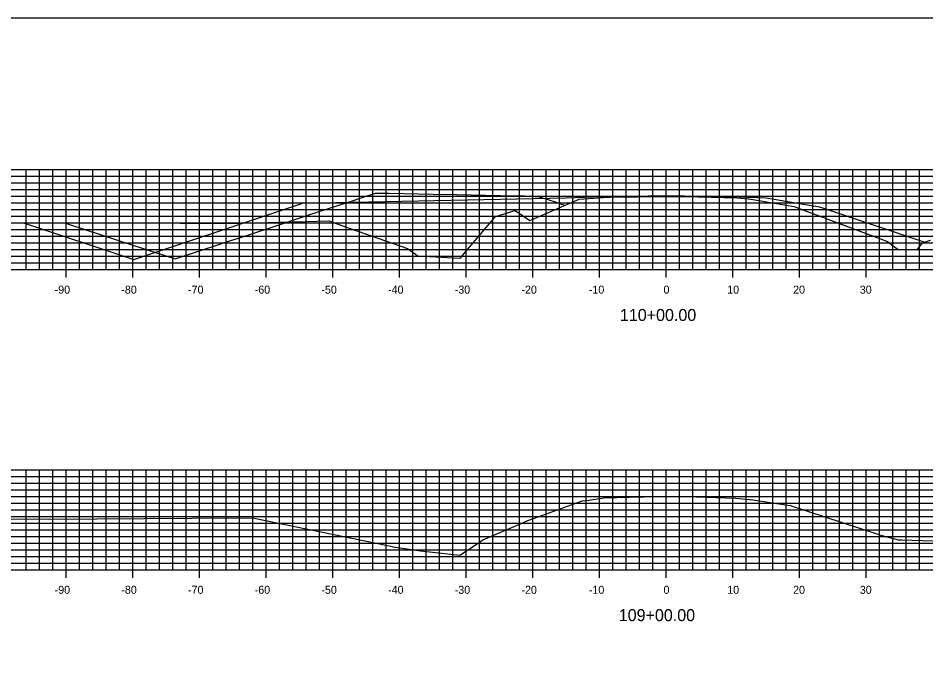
# Model space of a CAD drawing. Extents: x 1661012 to 1662122, y 670053 to 671852.
# Drawn here: x 1661094.8 to 1661230.9, y 671370.5 to 671466.8 of the extents above; entities that cross this region are included whole.
import ezdxf

# ---------------------------------------------------------------- set-up
doc = ezdxf.new("R2010")
doc.units = 0
for name, color, linetype in [('R_Concrete', 7, 'Continuous'), ('R_Concrete Hidden', 7, 'Continuous'), ('R_Erosion', 7, 'Continuous'), ('R_Exist Surface', 7, 'Continuous'), ('R_Proposed Road', 7, 'Continuous'), ('R_ROW Annot', 7, 'Continuous')]:
    doc.layers.add(name, color=color, linetype=linetype)

msp = doc.modelspace()

# ---------------------------------------------------------------- linework, layer by layer
at = {"layer": 'R_Concrete'}
for p, q in [((1661041.99, 671444.12), (1661341.99, 671444.12)), ((1661041.99, 671443.12), (1661341.99, 671443.12)), ((1661095.99, 671429.12), (1661095.99, 671444.12)), ((1661097.99, 671429.12), (1661097.99, 671444.12)), ((1661099.99, 671429.12), (1661099.99, 671444.12)), ((1661101.99, 671429.12), (1661101.99, 671444.12)), ((1661103.99, 671429.12), (1661103.99, 671444.12)), ((1661105.99, 671429.12), (1661105.99, 671444.12)), ((1661107.99, 671429.12), (1661107.99, 671444.12)), ((1661109.99, 671429.12), (1661109.99, 671444.12)), ((1661111.99, 671429.12), (1661111.99, 671444.12)), ((1661113.99, 671429.12), (1661113.99, 671444.12)), ((1661115.99, 671429.12), (1661115.99, 671444.12)), ((1661117.99, 671429.12), (1661117.99, 671444.12)), ((1661119.99, 671429.12), (1661119.99, 671444.12)), ((1661121.99, 671429.12), (1661121.99, 671444.12)), ((1661123.99, 671429.12), (1661123.99, 671444.12)), ((1661125.99, 671429.12), (1661125.99, 671444.12)), ((1661127.99, 671429.12), (1661127.99, 671444.12)), ((1661129.99, 671429.12), (1661129.99, 671444.12)), ((1661131.99, 671429.12), (1661131.99, 671444.12)), ((1661133.99, 671429.12), (1661133.99, 671444.12)), ((1661135.99, 671429.12), (1661135.99, 671444.12)), ((1661137.99, 671429.12), (1661137.99, 671444.12)), ((1661139.99, 671429.12), (1661139.99, 671444.12)), ((1661141.99, 671429.12), (1661141.99, 671444.12)), ((1661143.99, 671429.12), (1661143.99, 671444.12)), ((1661145.99, 671429.12), (1661145.99, 671444.12)), ((1661147.99, 671429.12), (1661147.99, 671444.12)), ((1661149.99, 671429.12), (1661149.99, 671444.12)), ((1661151.99, 671429.12), (1661151.99, 671444.12)), ((1661153.99, 671429.12), (1661153.99, 671444.12)), ((1661155.99, 671429.12), (1661155.99, 671444.12)), ((1661157.99, 671429.12), (1661157.99, 671444.12)), ((1661159.99, 671429.12), (1661159.99, 671444.12)), ((1661161.99, 671429.12), (1661161.99, 671444.12)), ((1661163.99, 671429.12), (1661163.99, 671444.12)), ((1661165.99, 671429.12), (1661165.99, 671444.12)), ((1661167.99, 671429.12), (1661167.99, 671444.12)), ((1661169.99, 671429.12), (1661169.99, 671444.12)), ((1661171.99, 671429.12), (1661171.99, 671444.12)), ((1661173.99, 671429.12), (1661173.99, 671444.12)), ((1661175.99, 671429.12), (1661175.99, 671444.12)), ((1661177.99, 671429.12), (1661177.99, 671444.12)), ((1661179.99, 671429.12), (1661179.99, 671444.12)), ((1661181.99, 671429.12), (1661181.99, 671444.12)), ((1661183.99, 671429.12), (1661183.99, 671444.12)), ((1661185.99, 671429.12), (1661185.99, 671444.12)), ((1661187.99, 671429.12), (1661187.99, 671444.12)), ((1661189.99, 671429.12), (1661189.99, 671444.12)), ((1661191.99, 671429.12), (1661191.99, 671444.12)), ((1661193.99, 671429.12), (1661193.99, 671444.12)), ((1661195.99, 671429.12), (1661195.99, 671444.12)), ((1661197.99, 671429.12), (1661197.99, 671444.12)), ((1661199.99, 671429.12), (1661199.99, 671444.12)), ((1661201.99, 671429.12), (1661201.99, 671444.12)), ((1661203.99, 671429.12), (1661203.99, 671444.12)), ((1661205.99, 671429.12), (1661205.99, 671444.12)), ((1661207.99, 671429.12), (1661207.99, 671444.12)), ((1661209.99, 671429.12), (1661209.99, 671444.12)), ((1661211.99, 671429.12), (1661211.99, 671444.12)), ((1661213.99, 671429.12), (1661213.99, 671444.12)), ((1661215.99, 671429.12), (1661215.99, 671444.12)), ((1661217.99, 671429.12), (1661217.99, 671444.12)), ((1661219.99, 671429.12), (1661219.99, 671444.12)), ((1661221.99, 671429.12), (1661221.99, 671444.12)), ((1661223.99, 671429.12), (1661223.99, 671444.12)), ((1661225.99, 671429.12), (1661225.99, 671444.12)), ((1661227.99, 671429.12), (1661227.99, 671444.12)), ((1661229.99, 671429.12), (1661229.99, 671444.12)), ((1661041.99, 671442.12), (1661341.99, 671442.12)), ((1661041.99, 671441.12), (1661341.99, 671441.12)), ((1661041.99, 671440.12), (1661341.99, 671440.12)), ((1661041.99, 671439.12), (1661341.99, 671439.12)), ((1661041.99, 671438.12), (1661341.99, 671438.12)), ((1661041.99, 671437.12), (1661341.99, 671437.12)), ((1661041.99, 671436.12), (1661341.99, 671436.12)), ((1661041.99, 671435.12), (1661341.99, 671435.12)), ((1661041.99, 671434.12), (1661341.99, 671434.12)), ((1661041.99, 671433.12), (1661341.99, 671433.12)), ((1661041.99, 671432.12), (1661341.99, 671432.12)), ((1661041.99, 671431.12), (1661341.99, 671431.12)), ((1661041.99, 671430.12), (1661341.99, 671430.12)), ((1661095.99, 671429.12), (1661095.99, 671429.72)), ((1661097.99, 671429.12), (1661097.99, 671429.72)), ((1661099.99, 671429.12), (1661099.99, 671429.72)), ((1661101.99, 671427.92), (1661101.99, 671430.32)), ((1661103.99, 671429.12), (1661103.99, 671429.72)), ((1661105.99, 671429.12), (1661105.99, 671429.72)), ((1661107.99, 671429.12), (1661107.99, 671429.72)), ((1661109.99, 671429.12), (1661109.99, 671429.72)), ((1661111.99, 671427.92), (1661111.99, 671430.32)), ((1661113.99, 671429.12), (1661113.99, 671429.72)), ((1661115.99, 671429.12), (1661115.99, 671429.72)), ((1661117.99, 671429.12), (1661117.99, 671429.72)), ((1661119.99, 671429.12), (1661119.99, 671429.72)), ((1661121.99, 671427.92), (1661121.99, 671430.32)), ((1661123.99, 671429.12), (1661123.99, 671429.72)), ((1661125.99, 671429.12), (1661125.99, 671429.72)), ((1661127.99, 671429.12), (1661127.99, 671429.72)), ((1661129.99, 671429.12), (1661129.99, 671429.72)), ((1661131.99, 671427.92), (1661131.99, 671430.32)), ((1661133.99, 671429.12), (1661133.99, 671429.72)), ((1661135.99, 671429.12), (1661135.99, 671429.72)), ((1661137.99, 671429.12), (1661137.99, 671429.72)), ((1661139.99, 671429.12), (1661139.99, 671429.72)), ((1661141.99, 671427.92), (1661141.99, 671430.32)), ((1661143.99, 671429.12), (1661143.99, 671429.72)), ((1661145.99, 671429.12), (1661145.99, 671429.72)), ((1661147.99, 671429.12), (1661147.99, 671429.72)), ((1661149.99, 671429.12), (1661149.99, 671429.72)), ((1661151.99, 671427.92), (1661151.99, 671430.32)), ((1661153.99, 671429.12), (1661153.99, 671429.72)), ((1661155.99, 671429.12), (1661155.99, 671429.72)), ((1661157.99, 671429.12), (1661157.99, 671429.72)), ((1661159.99, 671429.12), (1661159.99, 671429.72)), ((1661161.99, 671427.92), (1661161.99, 671430.32)), ((1661163.99, 671429.12), (1661163.99, 671429.72)), ((1661165.99, 671429.12), (1661165.99, 671429.72)), ((1661167.99, 671429.12), (1661167.99, 671429.72)), ((1661169.99, 671429.12), (1661169.99, 671429.72)), ((1661171.99, 671427.92), (1661171.99, 671430.32)), ((1661173.99, 671429.12), (1661173.99, 671429.72)), ((1661175.99, 671429.12), (1661175.99, 671429.72)), ((1661177.99, 671429.12), (1661177.99, 671429.72)), ((1661179.99, 671429.12), (1661179.99, 671429.72)), ((1661181.99, 671427.92), (1661181.99, 671430.32)), ((1661183.99, 671429.12), (1661183.99, 671429.72)), ((1661185.99, 671429.12), (1661185.99, 671429.72)), ((1661187.99, 671429.12), (1661187.99, 671429.72)), ((1661189.99, 671429.12), (1661189.99, 671429.72)), ((1661191.99, 671427.92), (1661191.99, 671430.32)), ((1661193.99, 671429.12), (1661193.99, 671429.72)), ((1661195.99, 671429.12), (1661195.99, 671429.72)), ((1661197.99, 671429.12), (1661197.99, 671429.72)), ((1661199.99, 671429.12), (1661199.99, 671429.72)), ((1661201.99, 671427.92), (1661201.99, 671430.32)), ((1661203.99, 671429.12), (1661203.99, 671429.72)), ((1661205.99, 671429.12), (1661205.99, 671429.72)), ((1661207.99, 671429.12), (1661207.99, 671429.72)), ((1661209.99, 671429.12), (1661209.99, 671429.72)), ((1661211.99, 671427.92), (1661211.99, 671430.32)), ((1661213.99, 671429.12), (1661213.99, 671429.72)), ((1661215.99, 671429.12), (1661215.99, 671429.72)), ((1661217.99, 671429.12), (1661217.99, 671429.72)), ((1661219.99, 671429.12), (1661219.99, 671429.72)), ((1661221.99, 671427.92), (1661221.99, 671430.32)), ((1661223.99, 671429.12), (1661223.99, 671429.72)), ((1661225.99, 671429.12), (1661225.99, 671429.72)), ((1661227.99, 671429.12), (1661227.99, 671429.72)), ((1661229.99, 671429.12), (1661229.99, 671429.72)), ((1661041.99, 671429.12), (1661341.99, 671429.12)), ((1661041.99, 671399.12), (1661341.99, 671399.12)), ((1661041.99, 671398.12), (1661341.99, 671398.12)), ((1661095.99, 671384.12), (1661095.99, 671399.12)), ((1661097.99, 671384.12), (1661097.99, 671399.12)), ((1661099.99, 671384.12), (1661099.99, 671399.12)), ((1661101.99, 671384.12), (1661101.99, 671399.12)), ((1661103.99, 671384.12), (1661103.99, 671399.12)), ((1661105.99, 671384.12), (1661105.99, 671399.12)), ((1661107.99, 671384.12), (1661107.99, 671399.12)), ((1661109.99, 671384.12), (1661109.99, 671399.12)), ((1661111.99, 671384.12), (1661111.99, 671399.12)), ((1661113.99, 671384.12), (1661113.99, 671399.12)), ((1661115.99, 671384.12), (1661115.99, 671399.12)), ((1661117.99, 671384.12), (1661117.99, 671399.12)), ((1661119.99, 671384.12), (1661119.99, 671399.12)), ((1661121.99, 671384.12), (1661121.99, 671399.12)), ((1661123.99, 671384.12), (1661123.99, 671399.12)), ((1661125.99, 671384.12), (1661125.99, 671399.12)), ((1661127.99, 671384.12), (1661127.99, 671399.12)), ((1661129.99, 671384.12), (1661129.99, 671399.12)), ((1661131.99, 671384.12), (1661131.99, 671399.12)), ((1661133.99, 671384.12), (1661133.99, 671399.12)), ((1661135.99, 671384.12), (1661135.99, 671399.12)), ((1661137.99, 671384.12), (1661137.99, 671399.12)), ((1661139.99, 671384.12), (1661139.99, 671399.12)), ((1661141.99, 671384.12), (1661141.99, 671399.12)), ((1661143.99, 671384.12), (1661143.99, 671399.12)), ((1661145.99, 671384.12), (1661145.99, 671399.12)), ((1661147.99, 671384.12), (1661147.99, 671399.12)), ((1661149.99, 671384.12), (1661149.99, 671399.12)), ((1661151.99, 671384.12), (1661151.99, 671399.12)), ((1661153.99, 671384.12), (1661153.99, 671399.12)), ((1661155.99, 671384.12), (1661155.99, 671399.12)), ((1661157.99, 671384.12), (1661157.99, 671399.12)), ((1661159.99, 671384.12), (1661159.99, 671399.12)), ((1661161.99, 671384.12), (1661161.99, 671399.12)), ((1661163.99, 671384.12), (1661163.99, 671399.12)), ((1661165.99, 671384.12), (1661165.99, 671399.12)), ((1661167.99, 671384.12), (1661167.99, 671399.12)), ((1661169.99, 671384.12), (1661169.99, 671399.12)), ((1661171.99, 671384.12), (1661171.99, 671399.12)), ((1661173.99, 671384.12), (1661173.99, 671399.12)), ((1661175.99, 671384.12), (1661175.99, 671399.12)), ((1661177.99, 671384.12), (1661177.99, 671399.12)), ((1661179.99, 671384.12), (1661179.99, 671399.12)), ((1661181.99, 671384.12), (1661181.99, 671399.12)), ((1661183.99, 671384.12), (1661183.99, 671399.12)), ((1661185.99, 671384.12), (1661185.99, 671399.12)), ((1661187.99, 671384.12), (1661187.99, 671399.12)), ((1661189.99, 671384.12), (1661189.99, 671399.12)), ((1661191.99, 671384.12), (1661191.99, 671399.12)), ((1661193.99, 671384.12), (1661193.99, 671399.12)), ((1661195.99, 671384.12), (1661195.99, 671399.12)), ((1661197.99, 671384.12), (1661197.99, 671399.12)), ((1661199.99, 671384.12), (1661199.99, 671399.12)), ((1661201.99, 671384.12), (1661201.99, 671399.12)), ((1661203.99, 671384.12), (1661203.99, 671399.12)), ((1661205.99, 671384.12), (1661205.99, 671399.12)), ((1661207.99, 671384.12), (1661207.99, 671399.12)), ((1661209.99, 671384.12), (1661209.99, 671399.12)), ((1661211.99, 671384.12), (1661211.99, 671399.12)), ((1661213.99, 671384.12), (1661213.99, 671399.12)), ((1661215.99, 671384.12), (1661215.99, 671399.12)), ((1661217.99, 671384.12), (1661217.99, 671399.12)), ((1661219.99, 671384.12), (1661219.99, 671399.12)), ((1661221.99, 671384.12), (1661221.99, 671399.12)), ((1661223.99, 671384.12), (1661223.99, 671399.12)), ((1661225.99, 671384.12), (1661225.99, 671399.12)), ((1661227.99, 671384.12), (1661227.99, 671399.12)), ((1661229.99, 671384.12), (1661229.99, 671399.12)), ((1661041.99, 671397.12), (1661341.99, 671397.12)), ((1661041.99, 671396.12), (1661341.99, 671396.12)), ((1661041.99, 671395.12), (1661341.99, 671395.12)), ((1661041.99, 671394.12), (1661341.99, 671394.12)), ((1661041.99, 671393.12), (1661341.99, 671393.12)), ((1661041.99, 671392.12), (1661341.99, 671392.12)), ((1661041.99, 671391.12), (1661341.99, 671391.12)), ((1661041.99, 671390.12), (1661341.99, 671390.12)), ((1661041.99, 671389.12), (1661341.99, 671389.12)), ((1661041.99, 671388.12), (1661341.99, 671388.12)), ((1661041.99, 671387.12), (1661341.99, 671387.12)), ((1661041.99, 671386.12), (1661341.99, 671386.12)), ((1661041.99, 671385.12), (1661341.99, 671385.12)), ((1661095.99, 671384.12), (1661095.99, 671384.72)), ((1661097.99, 671384.12), (1661097.99, 671384.72)), ((1661099.99, 671384.12), (1661099.99, 671384.72)), ((1661101.99, 671382.92), (1661101.99, 671385.32)), ((1661103.99, 671384.12), (1661103.99, 671384.72)), ((1661105.99, 671384.12), (1661105.99, 671384.72)), ((1661107.99, 671384.12), (1661107.99, 671384.72)), ((1661109.99, 671384.12), (1661109.99, 671384.72)), ((1661111.99, 671382.92), (1661111.99, 671385.32)), ((1661113.99, 671384.12), (1661113.99, 671384.72)), ((1661115.99, 671384.12), (1661115.99, 671384.72)), ((1661117.99, 671384.12), (1661117.99, 671384.72)), ((1661119.99, 671384.12), (1661119.99, 671384.72)), ((1661121.99, 671382.92), (1661121.99, 671385.32)), ((1661123.99, 671384.12), (1661123.99, 671384.72)), ((1661125.99, 671384.12), (1661125.99, 671384.72)), ((1661127.99, 671384.12), (1661127.99, 671384.72)), ((1661129.99, 671384.12), (1661129.99, 671384.72)), ((1661131.99, 671382.92), (1661131.99, 671385.32)), ((1661133.99, 671384.12), (1661133.99, 671384.72)), ((1661135.99, 671384.12), (1661135.99, 671384.72)), ((1661137.99, 671384.12), (1661137.99, 671384.72)), ((1661139.99, 671384.12), (1661139.99, 671384.72)), ((1661141.99, 671382.92), (1661141.99, 671385.32)), ((1661143.99, 671384.12), (1661143.99, 671384.72)), ((1661145.99, 671384.12), (1661145.99, 671384.72)), ((1661147.99, 671384.12), (1661147.99, 671384.72)), ((1661149.99, 671384.12), (1661149.99, 671384.72)), ((1661151.99, 671382.92), (1661151.99, 671385.32)), ((1661153.99, 671384.12), (1661153.99, 671384.72)), ((1661155.99, 671384.12), (1661155.99, 671384.72)), ((1661157.99, 671384.12), (1661157.99, 671384.72)), ((1661159.99, 671384.12), (1661159.99, 671384.72)), ((1661161.99, 671382.92), (1661161.99, 671385.32)), ((1661163.99, 671384.12), (1661163.99, 671384.72)), ((1661165.99, 671384.12), (1661165.99, 671384.72)), ((1661167.99, 671384.12), (1661167.99, 671384.72)), ((1661169.99, 671384.12), (1661169.99, 671384.72)), ((1661171.99, 671382.92), (1661171.99, 671385.32)), ((1661173.99, 671384.12), (1661173.99, 671384.72)), ((1661175.99, 671384.12), (1661175.99, 671384.72)), ((1661177.99, 671384.12), (1661177.99, 671384.72)), ((1661179.99, 671384.12), (1661179.99, 671384.72)), ((1661181.99, 671382.92), (1661181.99, 671385.32)), ((1661183.99, 671384.12), (1661183.99, 671384.72)), ((1661185.99, 671384.12), (1661185.99, 671384.72)), ((1661187.99, 671384.12), (1661187.99, 671384.72)), ((1661189.99, 671384.12), (1661189.99, 671384.72)), ((1661191.99, 671382.92), (1661191.99, 671385.32)), ((1661193.99, 671384.12), (1661193.99, 671384.72)), ((1661195.99, 671384.12), (1661195.99, 671384.72)), ((1661197.99, 671384.12), (1661197.99, 671384.72)), ((1661199.99, 671384.12), (1661199.99, 671384.72)), ((1661201.99, 671382.92), (1661201.99, 671385.32)), ((1661203.99, 671384.12), (1661203.99, 671384.72)), ((1661205.99, 671384.12), (1661205.99, 671384.72)), ((1661207.99, 671384.12), (1661207.99, 671384.72)), ((1661209.99, 671384.12), (1661209.99, 671384.72)), ((1661211.99, 671382.92), (1661211.99, 671385.32)), ((1661213.99, 671384.12), (1661213.99, 671384.72)), ((1661215.99, 671384.12), (1661215.99, 671384.72)), ((1661217.99, 671384.12), (1661217.99, 671384.72)), ((1661219.99, 671384.12), (1661219.99, 671384.72)), ((1661221.99, 671382.92), (1661221.99, 671385.32)), ((1661223.99, 671384.12), (1661223.99, 671384.72)), ((1661225.99, 671384.12), (1661225.99, 671384.72)), ((1661227.99, 671384.12), (1661227.99, 671384.72)), ((1661229.99, 671384.12), (1661229.99, 671384.72)), ((1661041.99, 671384.12), (1661341.99, 671384.12))]:
    msp.add_line(p, q, dxfattribs=at)
at = {"layer": 'R_Erosion'}
for points in [[(1661073.27, 671436.14), (1661096.5, 671436.14), (1661103.31, 671436.14), (1661119.17, 671436.08), (1661119.39, 671436.09), (1661126.61, 671436.02), (1661137.83, 671436.34), (1661141.38, 671436.44), (1661144.62, 671435.31), (1661153.18, 671432.3), (1661154.72, 671431.17), (1661160.98, 671430.86), (1661161.17, 671430.87), (1661161.38, 671431.17), (1661166.4, 671437.07), (1661169.36, 671437.99), (1661171.54, 671436.49), (1661177.46, 671439.02), (1661178.92, 671439.66), (1661182.56, 671439.92), (1661183.58, 671439.97), (1661191.8, 671440.07), (1661193.4, 671440.09), (1661194.86, 671440.06), (1661202.62, 671439.87), (1661204.29, 671439.73), (1661204.4, 671439.72), (1661209.14, 671438.91), (1661211.18, 671438.56), (1661211.41, 671438.48), (1661225.17, 671433.36), (1661225.81, 671432.82), (1661226.8, 671432.14), (1661227.48, 671432.14), (1661229.62, 671432.07), (1661229.77, 671432.29), (1661230.45, 671433.14), (1661231.62, 671433.55)], [(1661082.7, 671391.78), (1661099.45, 671391.69), (1661120.84, 671391.86), (1661129.96, 671391.91), (1661150.72, 671387.65), (1661151.3, 671387.52), (1661151.41, 671387.51), (1661155.14, 671386.97), (1661156.49, 671386.81), (1661161.05, 671386.31), (1661163.48, 671387.93), (1661164.49, 671388.61), (1661170.25, 671391.06), (1661171.25, 671391.5), (1661172.22, 671391.85), (1661179.39, 671394.44), (1661180.02, 671394.52), (1661182.7, 671394.9), (1661186.48, 671394.99), (1661193.08, 671395.16), (1661196.54, 671395.05), (1661202.44, 671394.86), (1661204.52, 671394.68), (1661204.58, 671394.67), (1661204.65, 671394.66), (1661210.57, 671393.77), (1661223.59, 671389.49), (1661223.91, 671389.39), (1661223.96, 671389.37), (1661226.76, 671388.62), (1661227.35, 671388.61), (1661236.52, 671388.3)]]:
    msp.add_lwpolyline(points, dxfattribs=at)
at = {"layer": 'R_Exist Surface'}
for p, q in [((1661041.99, 671429.12), (1661341.99, 671429.12)), ((1661041.99, 671384.12), (1661341.99, 671384.12))]:
    msp.add_line(p, q, dxfattribs=at)
at = {"layer": 'R_Proposed Road'}
msp.add_lwpolyline([(1661011.99, 671274.12), (1661371.99, 671274.12), (1661371.99, 671466.82), (1661011.99, 671466.82)], close=True, dxfattribs=at)
at = {"layer": 'R_ROW Annot'}
for points in [[(1661095.62, 671436.14), (1661112.16, 671430.63), (1661137.49, 671439.07), (1661169.58, 671439.71), (1661176.99, 671439.86), (1661180.99, 671440.02), (1661191.99, 671440.24), (1661202.99, 671440.02), (1661206.99, 671439.86), (1661214.4, 671438.63), (1661214.99, 671438.53), (1661230.8, 671433.26)], [(1661101.79, 671436.14), (1661102.09, 671436.04), (1661102.38, 671435.95), (1661111.87, 671432.86), (1661118.37, 671430.75), (1661121.69, 671431.84), (1661125.05, 671432.94), (1661126.72, 671433.48), (1661127.84, 671433.85), (1661132.77, 671435.46), (1661138.26, 671437.26), (1661139.94, 671437.81), (1661144.13, 671439.18), (1661144.31, 671439.23), (1661144.49, 671439.3), (1661146.7, 671440.01), (1661148.4, 671440.57), (1661149.91, 671440.57), (1661150.43, 671440.57), (1661157.06, 671440.43), (1661160.6, 671440.37), (1661169.22, 671440.2), (1661170.13, 671440.18), (1661170.77, 671440.17), (1661172.35, 671440.1), (1661172.8, 671440.09), (1661173.77, 671439.77), (1661175.92, 671439.07), (1661176.26, 671438.95), (1661176.47, 671438.89), (1661176.61, 671438.84), (1661176.84, 671438.76)]]:
    msp.add_lwpolyline(points, dxfattribs=at)

# ---------------------------------------------------------------- texts
at = {"layer": 'R_Concrete Hidden'}
for s, height, p in [('-90', 1.2, (1661100.28, 671425.52)), ('-80', 1.2, (1661110.28, 671425.52)), ('-70', 1.2, (1661120.28, 671425.52)), ('-60', 1.2, (1661130.28, 671425.52)), ('-50', 1.2, (1661140.28, 671425.52)), ('-40', 1.2, (1661150.28, 671425.52)), ('-30', 1.2, (1661160.28, 671425.52)), ('-20', 1.2, (1661170.28, 671425.52)), ('-10', 1.2, (1661180.39, 671425.52)), ('0', 1.2, (1661191.59, 671425.52)), ('10', 1.2, (1661201.14, 671425.52)), ('20', 1.2, (1661211.02, 671425.52)), ('30', 1.2, (1661221.02, 671425.52)), ('110+00.00', 1.8, (1661185.05, 671421.42)), ('-90', 1.2, (1661100.28, 671380.52)), ('-80', 1.2, (1661110.28, 671380.52)), ('-70', 1.2, (1661120.28, 671380.52)), ('-60', 1.2, (1661130.28, 671380.52)), ('-50', 1.2, (1661140.28, 671380.52)), ('-40', 1.2, (1661150.28, 671380.52)), ('-30', 1.2, (1661160.28, 671380.52)), ('-20', 1.2, (1661170.28, 671380.52)), ('-10', 1.2, (1661180.39, 671380.52)), ('0', 1.2, (1661191.59, 671380.52)), ('10', 1.2, (1661201.14, 671380.52)), ('20', 1.2, (1661211.02, 671380.52)), ('30', 1.2, (1661221.02, 671380.52)), ('109+00.00', 1.8, (1661184.88, 671376.42))]:
    msp.add_text(s, height=height, dxfattribs=at).set_placement(p)

doc.saveas('drawing.dxf')
